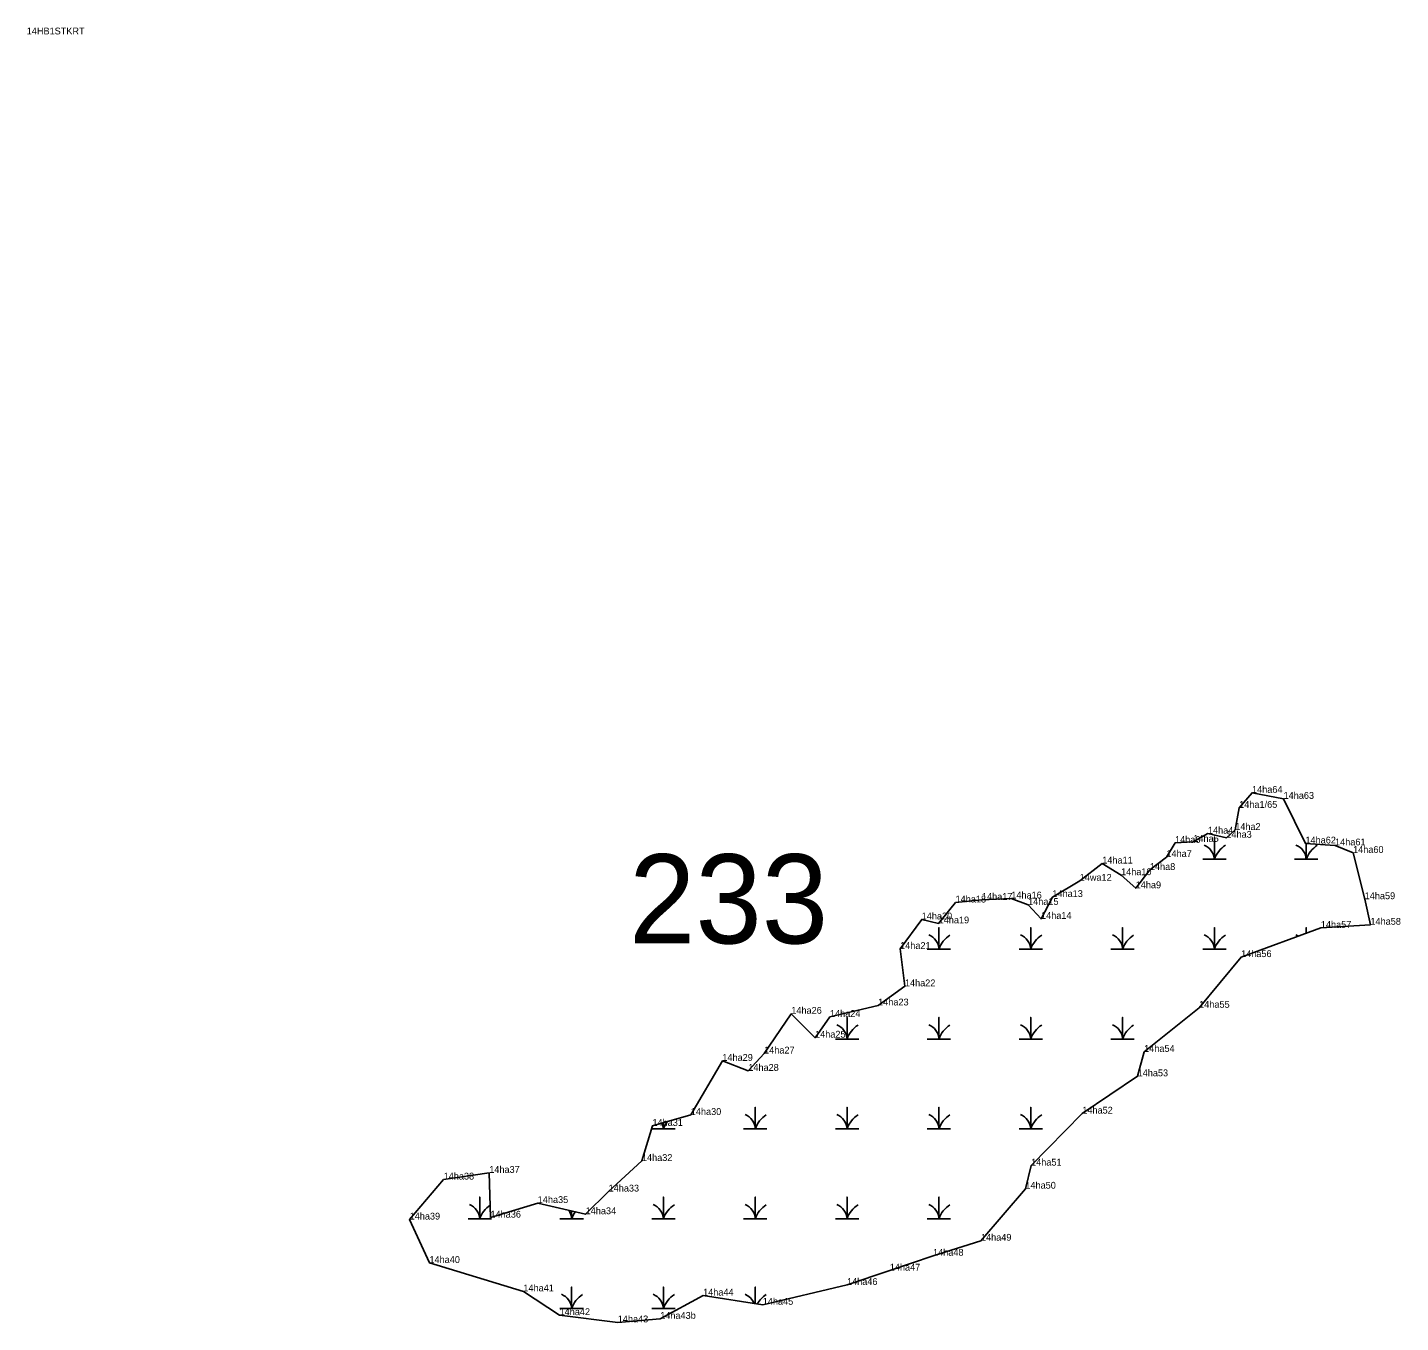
# Model space of a CAD drawing. Extents: x 2072529 to 2268796, y 436423 to 470406.
# Drawn here: x 2254585 to 2255590, y 442680 to 443629 of the extents above; entities that cross this region are included whole.
import ezdxf

# ---------------------------------------------------------------- set-up
doc = ezdxf.new("R2010")
doc.units = 0
for name, color, linetype in [('Default', 7, 'Continuous'), ('Exist Environmental Wetland Boundary Cogo Comment', 7, 'Continuous'), ('Exist Environmental Wetland Boundary Cogo Point CELL', 7, 'Continuous'), ('Old_Level_20', 7, 'Continuous')]:
    doc.layers.add(name, color=color, linetype=linetype)

msp = doc.modelspace()

# ---------------------------------------------------------------- linework, layer by layer
at = {"layer": 'Exist Environmental Wetland Boundary Cogo Point CELL'}
for points in [[(2255445.3, 443019.4), (2255453.9, 443019.4), (2255453.9, 443035.2), (2255453.9, 443019.4), (2255462.5, 443019.4)], [(2255512.5, 443019.4), (2255521.1, 443019.4), (2255521.1, 443030.9)], [(2255521.1, 443030.9), (2255521.1, 443019.4), (2255529.7, 443019.4)], [(2255243.5, 442953.6), (2255252.1, 442953.6), (2255252.1, 442969.4), (2255252.1, 442953.6), (2255260.7, 442953.6)], [(2255310.8, 442953.6), (2255319.4, 442953.6), (2255319.4, 442969.4), (2255319.4, 442953.6), (2255328, 442953.6)], [(2255378, 442953.6), (2255386.6, 442953.6), (2255386.6, 442969.4), (2255386.6, 442953.6), (2255395.2, 442953.6)], [(2255445.3, 442953.6), (2255453.9, 442953.6), (2255453.9, 442969.4), (2255453.9, 442953.6), (2255462.5, 442953.6)], [(2255521.1, 442965.3), (2255521.1, 442969.4), (2255521.1, 442965.3)], [(2255176.3, 442887.8), (2255184.9, 442887.8), (2255184.9, 442903.6), (2255184.9, 442887.8), (2255193.5, 442887.8)], [(2255243.5, 442887.8), (2255252.1, 442887.8), (2255252.1, 442903.6), (2255252.1, 442887.8), (2255260.7, 442887.8)], [(2255310.8, 442887.8), (2255319.4, 442887.8), (2255319.4, 442903.6), (2255319.4, 442887.8), (2255328, 442887.8)], [(2255378, 442887.8), (2255386.6, 442887.8), (2255386.6, 442903.6), (2255386.6, 442887.8), (2255395.2, 442887.8)], [(2255109, 442822), (2255117.6, 442822), (2255117.6, 442837.8), (2255117.6, 442822), (2255126.2, 442822)], [(2255176.3, 442822), (2255184.9, 442822), (2255184.9, 442837.8), (2255184.9, 442822), (2255193.5, 442822)], [(2255243.5, 442822), (2255252.1, 442822), (2255252.1, 442837.8), (2255252.1, 442822), (2255260.7, 442822)], [(2255310.8, 442822), (2255319.4, 442822), (2255319.4, 442837.8), (2255319.4, 442822), (2255328, 442822)], [(2255041.8, 442822), (2255050.4, 442822), (2255050.4, 442826.5)], [(2255050.4, 442826.5), (2255050.4, 442822), (2255059, 442822)], [(2254907.3, 442756.2), (2254915.9, 442756.2), (2254915.9, 442772), (2254915.9, 442756.2), (2254924.5, 442756.2)], [(2255041.8, 442756.2), (2255050.4, 442756.2), (2255050.4, 442772), (2255050.4, 442756.2), (2255059, 442756.2)], [(2255109, 442756.2), (2255117.6, 442756.2), (2255117.6, 442772), (2255117.6, 442756.2), (2255126.2, 442756.2)], [(2255176.3, 442756.2), (2255184.9, 442756.2), (2255184.9, 442772), (2255184.9, 442756.2), (2255193.5, 442756.2)], [(2255243.5, 442756.2), (2255252.1, 442756.2), (2255252.1, 442772), (2255252.1, 442756.2), (2255260.7, 442756.2)], [(2254974.5, 442756.2), (2254983.1, 442756.2), (2254983.1, 442761.9)], [(2254983.1, 442761.9), (2254983.1, 442756.2), (2254991.7, 442756.2)], [(2254974.5, 442690.4), (2254983.1, 442690.4), (2254983.1, 442706.2), (2254983.1, 442690.4), (2254991.7, 442690.4)], [(2255041.8, 442690.4), (2255050.4, 442690.4), (2255050.4, 442706.2), (2255050.4, 442690.4), (2255059, 442690.4)], [(2255117.6, 442694), (2255117.6, 442706.2), (2255117.6, 442694)]]:
    msp.add_lwpolyline(points, dxfattribs=at)
for centre, radius, start, end in [((2255441.6, 443018.5), 12.3, 4.1403, 67.535), ((2255508.9, 443018.5), 12.3, 4.1403, 67.535), ((2255472.1, 443013.4), 19.2, 122.1274, 161.6222), ((2255539.4, 443013.4), 19.2, 122.1274, 161.6222), ((2255239.9, 442952.7), 12.3, 4.1403, 67.535), ((2255270.4, 442947.6), 19.2, 122.1274, 161.6222), ((2255307.1, 442952.7), 12.3, 4.1403, 67.535), ((2255337.6, 442947.6), 19.2, 122.1274, 161.6222), ((2255374.4, 442952.7), 12.3, 4.1403, 67.535), ((2255404.9, 442947.6), 19.2, 122.1274, 161.6222), ((2255441.6, 442952.7), 12.3, 4.1403, 67.535), ((2255472.1, 442947.6), 19.2, 122.1274, 161.6222), ((2255508.9, 442952.7), 12.3, 58.2333, 67.535), ((2255172.6, 442886.9), 12.3, 4.1403, 67.535), ((2255203.1, 442881.8), 19.2, 122.1274, 161.6222), ((2255239.9, 442886.9), 12.3, 4.1403, 67.535), ((2255270.4, 442881.8), 19.2, 122.1274, 161.6222), ((2255307.1, 442886.9), 12.3, 4.1403, 67.535), ((2255337.6, 442881.8), 19.2, 122.1274, 161.6222), ((2255374.4, 442886.9), 12.3, 4.1403, 67.535), ((2255404.9, 442881.8), 19.2, 122.1274, 161.6222), ((2255105.4, 442821.1), 12.3, 4.1403, 67.535), ((2255135.9, 442816), 19.2, 122.1274, 161.6222), ((2255172.6, 442821.1), 12.3, 4.1403, 67.535), ((2255203.1, 442816), 19.2, 122.1274, 161.6222), ((2255239.9, 442821.1), 12.3, 4.1403, 67.535), ((2255270.4, 442816), 19.2, 122.1274, 161.6222), ((2255307.1, 442821.1), 12.3, 4.1403, 67.535), ((2255337.6, 442816), 19.2, 122.1274, 161.6222), ((2255038.1, 442821.1), 12.3, 4.1403, 24.2212), ((2255068.6, 442816), 19.2, 144.059, 161.6222), ((2254903.6, 442755.3), 12.3, 4.1403, 67.535), ((2254934.1, 442750.2), 19.2, 123.8007, 161.6222), ((2254970.9, 442755.3), 12.3, 4.1403, 35.0061), ((2255001.4, 442750.2), 19.2, 144.6594, 161.6222), ((2255038.1, 442755.3), 12.3, 4.1403, 67.535), ((2255068.6, 442750.2), 19.2, 122.1274, 161.6222), ((2255105.4, 442755.3), 12.3, 4.1403, 67.535), ((2255135.9, 442750.2), 19.2, 122.1274, 161.6222), ((2255172.6, 442755.3), 12.3, 4.1403, 67.535), ((2255203.1, 442750.2), 19.2, 122.1274, 161.6222), ((2255239.9, 442755.3), 12.3, 4.1403, 67.535), ((2255270.4, 442750.2), 19.2, 122.1274, 161.6222), ((2254970.9, 442689.5), 12.3, 4.1403, 67.535), ((2255001.4, 442684.4), 19.2, 122.1274, 161.6222), ((2255038.1, 442689.5), 12.3, 4.1403, 67.535), ((2255068.6, 442684.4), 19.2, 122.1274, 161.6222), ((2255105.4, 442689.5), 12.3, 22.0003, 67.535), ((2255135.9, 442684.4), 19.2, 122.1274, 150.6653)]:
    msp.add_arc(centre, radius, start, end, dxfattribs=at)
at = {"layer": 'Old_Level_20'}
for p, q in [((2255481.4, 443068.1), (2255481.4, 443068.1)), ((2255504.5, 443063.7), (2255504.5, 443063.7)), ((2255472, 443057.1), (2255472, 443057.1)), ((2255469.1, 443040.9), (2255469.1, 443040.9)), ((2255425, 443031.4), (2255425, 443031.4)), ((2255438.4, 443032.2), (2255438.4, 443032.2)), ((2255449.1, 443038.2), (2255449.1, 443038.2)), ((2255462.6, 443035.2), (2255462.6, 443035.2)), ((2255520.5, 443031), (2255520.5, 443031)), ((2255418.7, 443021.1), (2255418.7, 443021.1)), ((2255542.2, 443029.6), (2255542.2, 443029.6)), ((2255555.4, 443024.1), (2255555.4, 443024.1)), ((2255371.7, 443016.3), (2255371.7, 443016.3)), ((2255406.6, 443011.6), (2255406.6, 443011.6)), ((2255355.2, 443003.7), (2255355.2, 443003.7)), ((2255385.5, 443007.8), (2255385.5, 443007.8)), ((2255283.6, 442989.7), (2255283.6, 442989.7)), ((2255305.1, 442990.7), (2255305.1, 442990.7)), ((2255335.2, 442991.8), (2255335.2, 442991.8)), ((2255396.2, 442998.2), (2255396.2, 442998.2)), ((2255563.9, 442990.2), (2255563.9, 442990.2)), ((2255264.3, 442987.8), (2255264.3, 442987.8)), ((2255317.4, 442986), (2255317.4, 442986)), ((2255239.5, 442975.4), (2255239.5, 442975.4)), ((2255251.9, 442972.5), (2255251.9, 442972.5)), ((2255326.9, 442975.8), (2255326.9, 442975.8)), ((2255568.1, 442971.5), (2255568.1, 442971.5)), ((2255531.8, 442969.2), (2255531.8, 442969.2)), ((2255223.7, 442953.8), (2255223.7, 442953.8)), ((2255473.4, 442947.8), (2255473.4, 442947.8)), ((2255227.2, 442926.4), (2255227.2, 442926.4)), ((2255207.6, 442912.4), (2255207.6, 442912.4)), ((2255442.7, 442910.7), (2255442.7, 442910.7)), ((2255144, 442906.3), (2255144, 442906.3)), ((2255172.3, 442904), (2255172.3, 442904)), ((2255161.4, 442888.8), (2255161.4, 442888.8)), ((2255093.5, 442871.8), (2255093.5, 442871.8)), ((2255124.1, 442877.2), (2255124.1, 442877.2)), ((2255402.4, 442878.4), (2255402.4, 442878.4)), ((2255112.5, 442864.5), (2255112.5, 442864.5)), ((2255397.6, 442860.5), (2255397.6, 442860.5)), ((2255070.4, 442832.2), (2255070.4, 442832.2)), ((2255357.1, 442833.2), (2255357.1, 442833.2)), ((2255042.3, 442824.2), (2255042.3, 442824.2)), ((2255034.6, 442798.5), (2255034.6, 442798.5)), ((2254922.8, 442789.8), (2254922.8, 442789.8)), ((2255319.6, 442795.1), (2255319.6, 442795.1)), ((2254889.4, 442784.9), (2254889.4, 442784.9)), ((2255010.2, 442776.1), (2255010.2, 442776.1)), ((2255315.4, 442778.2), (2255315.4, 442778.2)), ((2254958.3, 442767.7), (2254958.3, 442767.7)), ((2254993.4, 442759.5), (2254993.4, 442759.5)), ((2254864.5, 442755.6), (2254864.5, 442755.6)), ((2254923.7, 442757), (2254923.7, 442757)), ((2255282.9, 442740.1), (2255282.9, 442740.1)), ((2255247.8, 442729.1), (2255247.8, 442729.1)), ((2254879, 442723.8), (2254879, 442723.8)), ((2255216.1, 442718.2), (2255216.1, 442718.2)), ((2254947.8, 442703), (2254947.8, 442703)), ((2255079.4, 442699.9), (2255079.4, 442699.9)), ((2255184.8, 442707.7), (2255184.8, 442707.7)), ((2255123.1, 442693.2), (2255123.1, 442693.2)), ((2254974.3, 442685.6), (2254974.3, 442685.6)), ((2255016.9, 442680.3), (2255016.9, 442680.3)), ((2255048, 442682.9), (2255048, 442682.9))]:
    msp.add_line(p, q, dxfattribs=at)
msp.add_lwpolyline([(2255472, 443057.1), (2255469.1, 443040.9), (2255462.6, 443035.2), (2255449.1, 443038.2), (2255438.4, 443032.2), (2255425, 443031.4), (2255418.7, 443021.1), (2255406.6, 443011.6), (2255396.2, 442998.2), (2255385.5, 443007.8), (2255371.7, 443016.3), (2255355.2, 443003.7), (2255335.2, 442991.8), (2255326.9, 442975.8), (2255317.4, 442986), (2255305.1, 442990.7), (2255283.6, 442989.7), (2255264.3, 442987.8), (2255251.9, 442972.5), (2255239.5, 442975.4), (2255223.7, 442953.8), (2255227.2, 442926.4), (2255207.6, 442912.4), (2255172.3, 442904), (2255161.4, 442888.8), (2255144, 442906.3), (2255124.1, 442877.2), (2255112.5, 442864.5), (2255093.5, 442871.8), (2255070.4, 442832.2), (2255042.3, 442824.2), (2255034.6, 442798.5), (2255010.2, 442776.1), (2254993.4, 442759.5), (2254958.3, 442767.7), (2254923.7, 442757), (2254922.8, 442789.8), (2254889.4, 442784.9), (2254864.5, 442755.6), (2254879, 442723.8), (2254947.8, 442703), (2254974.3, 442685.6), (2255016.9, 442680.3), (2255048, 442682.9), (2255079.4, 442699.9), (2255123.1, 442693.2), (2255184.8, 442707.7), (2255216.1, 442718.2), (2255247.8, 442729.1), (2255282.9, 442740.1), (2255315.4, 442778.2), (2255319.6, 442795.1), (2255357.1, 442833.2), (2255397.6, 442860.5), (2255402.4, 442878.4), (2255442.7, 442910.7), (2255473.4, 442947.8), (2255531.8, 442969.2), (2255568.1, 442971.5), (2255563.9, 442990.2), (2255555.4, 443024.1), (2255542.2, 443029.6), (2255520.5, 443031), (2255504.5, 443063.7), (2255481.4, 443068.1)], close=True, dxfattribs=at)

# ---------------------------------------------------------------- texts
at = {"layer": 'Default'}
msp.add_text('233', height=65.34, dxfattribs=at).set_placement((2255025.2, 442957.8))
at = {"layer": 'Exist Environmental Wetland Boundary Cogo Comment'}
for s, p in [('14HB1STKRT', (2254584.1, 443623.5)), ('14ha64', (2255481.4, 443068.1)), ('14ha1/65', (2255472, 443057.1)), ('14ha63', (2255504.5, 443063.7)), ('14ha4', (2255449.1, 443038.2)), ('14ha3', (2255462.6, 443035.2)), ('14ha2', (2255469.1, 443040.9)), ('14ha6', (2255425, 443031.4)), ('14ha5', (2255438.4, 443032.2)), ('14ha62', (2255520.5, 443031)), ('14ha61', (2255542.2, 443029.6)), ('14ha11', (2255371.7, 443016.3)), ('14ha7', (2255418.7, 443021.1)), ('14ha60', (2255555.4, 443024.1)), ('14ha10', (2255385.5, 443007.8)), ('14ha8', (2255406.6, 443011.6)), ('14wa12', (2255355.2, 443003.7)), ('14ha9', (2255396.2, 442998.2)), ('14ha18', (2255264.3, 442987.8)), ('14ha17', (2255283.6, 442989.7)), ('14ha16', (2255305.1, 442990.7)), ('14ha15', (2255317.4, 442986)), ('14ha13', (2255335.2, 442991.8)), ('14ha59', (2255563.9, 442990.2)), ('14ha20', (2255239.5, 442975.4)), ('14ha14', (2255326.9, 442975.8)), ('14ha19', (2255251.9, 442972.5)), ('14ha57', (2255531.8, 442969.2)), ('14ha58', (2255568.1, 442971.5)), ('14ha21', (2255223.7, 442953.8)), ('14ha56', (2255473.4, 442947.8)), ('14ha22', (2255227.2, 442926.4)), ('14ha26', (2255144, 442906.3)), ('14ha24', (2255172.3, 442904)), ('14ha23', (2255207.6, 442912.4)), ('14ha55', (2255442.7, 442910.7)), ('14ha25', (2255161.4, 442888.8)), ('14ha27', (2255124.1, 442877.2)), ('14ha54', (2255402.4, 442878.4)), ('14ha29', (2255093.5, 442871.8)), ('14ha28', (2255112.5, 442864.5)), ('14ha53', (2255397.6, 442860.5)), ('14ha31', (2255042.3, 442824.2)), ('14ha30', (2255070.4, 442832.2)), ('14ha52', (2255357.1, 442833.2)), ('14ha32', (2255034.6, 442798.5)), ('14ha51', (2255319.6, 442795.1)), ('14ha38', (2254889.4, 442784.9)), ('14ha37', (2254922.8, 442789.8)), ('14ha33', (2255010.2, 442776.1)), ('14ha50', (2255315.4, 442778.2)), ('14ha35', (2254958.3, 442767.7)), ('14ha39', (2254864.5, 442755.6)), ('14ha36', (2254923.7, 442757)), ('14ha34', (2254993.4, 442759.5)), ('14ha49', (2255282.9, 442740.1)), ('14ha40', (2254879, 442723.8)), ('14ha48', (2255247.8, 442729.1)), ('14ha47', (2255216.1, 442718.2)), ('14ha41', (2254947.8, 442703)), ('14ha46', (2255184.8, 442707.7)), ('14ha44', (2255079.4, 442699.9)), ('14ha45', (2255123.1, 442693.2)), ('14ha42', (2254974.3, 442685.6)), ('14ha43b', (2255048, 442682.9)), ('14ha43', (2255016.9, 442680.3))]:
    msp.add_text(s, height=5, dxfattribs=at).set_placement(p)

doc.saveas('drawing.dxf')
